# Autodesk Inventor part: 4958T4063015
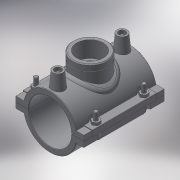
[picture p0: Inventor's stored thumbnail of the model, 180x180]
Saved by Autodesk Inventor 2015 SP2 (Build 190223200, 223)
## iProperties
Created: 2017-07
Part Number: 4958T4063015
Material: Generic
Description: PLASSON SADDLE 63X1.1/2" FEMALE BSPP
Document SubType Name: Modeling
Designer: KIM
Density: 1 g/cm^3
Appearance: Default
Author: KIM
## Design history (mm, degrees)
derived "4958T4.ipt"
feature "Solid1::4958T4.ipt"
tag "TaggingFeature1"
body "Solid1"
other parameters: "d0" = 63, "d1" = 78.75, "d3" = 15.75, "d4" = 118, "d5" = 0, "d6" = 0.1, "d8" = 0, "d19" = 6, "d20" = 6, "d21" = 70.8, "d23" = 0, "d24" = 35.4, "d26" = 0, "d27" = 3, "d28" = 3, "d29" = 3, "d30" = 24.00694, "d31" = 6, "d32" = 0, "d33" = 0, "d34" = 0.6, "d40" = 42.21, "d41" = 63, "d43" = 0, "d45" = 0, "d46" = 6.3, "d47" = 61.5, "d48" = 58.2985, "d50" = 0, "d51" = 44.845, "d52" = 24, "d53" = 0, "d54" = 35.876, "d56" = 0, "d57" = -9, "d58" = 0.5, "d59" = 0.1, "d60" = 0, "d61" = 0.5, "d64" = 1.34535, "d67" = 0.63, "d70" = 15, "d72" = 0, "d73" = 6, "d75" = 5, "d76" = 0, "d77" = 3.15, "d78" = 60.5, "d79" = 15, "d80" = 47.2, "d82" = 5 deg, "d84" = 4, "d85" = 14, "d86" = 0, "d87" = 3, "d88" = 0, "d89" = 1, "d90" = 1, "d91" = 94.4, "d92" = 0, "d93" = 0.5, "d94" = 33.15789, "d_" = 63, "Rp_" = 44.845, "L_" = 118, "d_t" = 6
